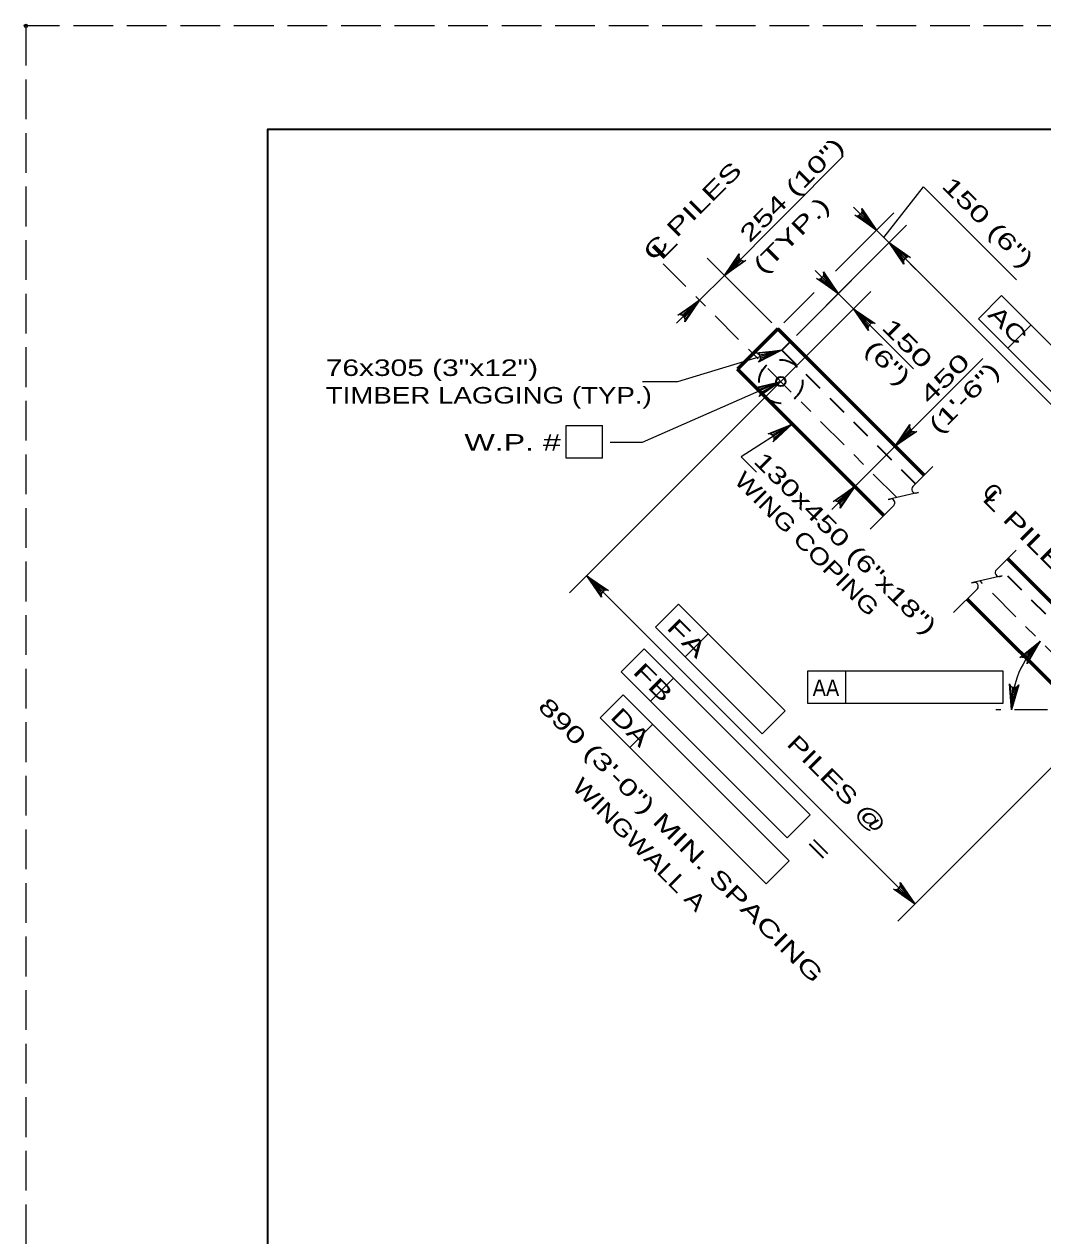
# Model space of a CAD drawing. Extents: x -6.4 to 73.1, y -66 to 0.
# Drawn here: x -0.01 to 7.37, y -8.76 to 0.01 of the extents above; entities that cross this region are included whole.
import ezdxf
from ezdxf.enums import TextEntityAlignment as Align

# ---------------------------------------------------------------- set-up
doc = ezdxf.new("R2010")
doc.units = 0
doc.header["$LTSCALE"] = 0.048
doc.header["$PDMODE"] = 32
doc.header["$PDSIZE"] = 0.024
for name, pattern in [('DOT_DASHED', [7.7, 5, -1.2, 0.3, -1.2]), ('LONG_DASHED', [7.5, 6, -1.5]), ('MEDIUM_DASHED', [4.5, 3, -1.5])]:
    doc.linetypes.add(name, pattern=pattern)
for name, color, linetype, lineweight in [('1', 7, 'Continuous', 13), ('2', 7, 'Continuous', 53), ('4', 7, 'Continuous', 25), ('5', 7, 'Continuous', 25), ('52', 7, 'Continuous', 25), ('63', 7, 'LONG_DASHED', 13)]:
    doc.layers.add(name, color=color, linetype=linetype, lineweight=lineweight)
doc.layers.add('62', color=7, linetype='Continuous')

msp = doc.modelspace()

# ---------------------------------------------------------------- hatches: boundary and pattern name
at = {"layer": '5'}
for points in [[(6.095, -1.38175), (6.06717, -1.40958), (6.16458, -1.47917)], [(6.3525, -1.63925), (6.32467, -1.66708), (6.25508, -1.56958)], [(5.13125, -1.70942), (5.15908, -1.73725), (5.06158, -1.80683)], [(5.81733, -1.84033), (5.7895, -1.86817), (5.88692, -1.93775)], [(4.784, -2.05658), (4.81183, -2.0845), (4.88142, -1.987)], [(6.09567, -2.11875), (6.06783, -2.14658), (5.99825, -2.04917)], [(5.47708, -2.34758), (5.36125, -2.37267), (5.367, -2.39142)], [(6.36883, -2.947), (6.39667, -2.97483), (6.29925, -3.04442)], [(5.9095, -3.40633), (5.93733, -3.43417), (6.00692, -3.33675)], [(4.16267, -4.05175), (4.13483, -4.07958), (4.06525, -3.98217)], [(6.37308, -6.26217), (6.34525, -6.29), (6.44267, -6.35958)]]:
    msp.add_hatch(color=256, dxfattribs=at).paths.add_polyline_path(points)

# ---------------------------------------------------------------- linework, layer by layer
at = {"layer": '1', "lineweight": 35}
msp.add_lwpolyline([(1.75, -21.25), (33.25, -21.25), (33.25, -0.75), (1.75, -0.75)], close=True, dxfattribs=at)
at = {"layer": '2'}
for p, q in [((5.44925, -2.1945), (5.15692, -2.48675)), ((6.50908, -3.25433), (5.44925, -2.1945)), ((6.21683, -3.54667), (5.15692, -2.48675)), ((7.91342, -4.65867), (7.1135, -3.85875)), ((7.74217, -5.072), (6.82125, -4.15108))]:
    msp.add_line(p, q, dxfattribs=at)
at = {"layer": '4', "linetype": 'MEDIUM_DASHED', "lineweight": 35}
for p, q in [((5.53975, -2.28492), (5.47708, -2.34758)), ((6.4465, -3.317), (5.47708, -2.34758)), ((8.08025, -4.95067), (7.05092, -3.92142))]:
    msp.add_line(p, q, dxfattribs=at)
msp.add_circle((5.4709, -2.5765), 0.15748, dxfattribs=at)
at = {"layer": '5'}
for p, q in [((5.06167, -1.80692), (5.9235, -0.94475)), ((6.1645, -1.47917), (5.99758, -1.31208)), ((5.86608, -1.77758), (6.28983, -1.35383)), ((5.58325, -2.24142), (6.38033, -1.44433)), ((6.37342, -1.68792), (6.16458, -1.47917)), ((8.62875, -3.94333), (6.25508, -1.56967)), ((5.40575, -2.151), (4.93633, -1.68158)), ((6.36642, -1.681), (6.44992, -1.7645)), ((4.88142, -1.987), (5.06158, -1.80683)), ((5.58325, -2.24142), (6.01217, -1.8125)), ((5.88692, -1.93775), (5.71992, -1.77075)), ((6.1235, -1.92383), (3.94, -4.10742)), ((4.88142, -1.987), (4.71442, -2.15408)), ((5.49275, -2.151), (5.71308, -1.93067)), ((5.88692, -1.93775), (5.99825, -2.04917)), ((7.06925, -1.95375), (6.90225, -2.12083)), ((7.06925, -1.95375), (8.27192, -3.15642)), ((5.99825, -2.04917), (6.43317, -2.48408)), ((6.90225, -2.12083), (8.10483, -3.32342)), ((7.28308, -2.16767), (7.11608, -2.33467)), ((6.29925, -3.04442), (6.93475, -2.40883)), ((3.91458, -3.12983), (3.91458, -2.89358)), ((3.91458, -2.89358), (4.17825, -2.89358)), ((4.17825, -3.12983), (4.17825, -2.89358)), ((6.00692, -3.33675), (6.29925, -3.04442)), ((6.28167, -3.02683), (6.4245, -3.16967)), ((4.17825, -3.12983), (3.91458, -3.12983)), ((6.57142, -3.192), (6.428, -3.3355)), ((5.98933, -3.31917), (6.13217, -3.462)), ((6.00692, -3.33675), (5.83992, -3.50375)), ((6.29058, -3.47283), (6.11783, -3.64567)), ((7.17617, -3.79608), (7.03275, -3.9395)), ((6.44267, -6.35958), (4.06525, -3.98217)), ((6.89542, -4.07683), (6.72258, -4.24967)), ((4.72975, -4.18875), (4.56275, -4.35575)), ((4.72975, -4.18875), (5.50158, -4.96058)), ((4.56275, -4.35575), (5.33458, -5.12758)), ((4.94358, -4.40258), (4.77658, -4.56958)), ((4.48025, -4.51117), (4.31325, -4.67825)), ((4.48025, -4.51117), (5.68292, -5.71383)), ((4.31325, -4.67825), (5.51583, -5.88083)), ((4.69408, -4.72508), (4.52708, -4.89208)), ((5.66692, -4.67183), (7.07892, -4.67183)), ((5.66692, -4.90808), (5.66692, -4.67183)), ((5.94067, -4.90808), (5.94067, -4.67183)), ((7.07892, -4.67183), (7.07892, -4.90808)), ((4.32917, -4.84467), (4.16217, -5.01167)), ((4.32917, -4.84467), (5.53183, -6.04733)), ((7.07892, -4.90808), (5.66692, -4.90808)), ((5.50158, -4.96058), (5.33458, -5.12758)), ((4.16217, -5.01167), (5.36483, -6.21433)), ((4.54308, -5.0585), (4.376, -5.22558)), ((7.43417, -5.36808), (6.31742, -6.48483)), ((5.68292, -5.71383), (5.51583, -5.88083)), ((5.53183, -6.04733), (5.36483, -6.21433))]:
    msp.add_line(p, q, dxfattribs=at)
at = {"layer": '5', "linetype": 'DOT_DASHED'}
for p, q in [((6.31042, -3.416), (4.61825, -1.72383)), ((7.93725, -5.04283), (6.91458, -4.02017)), ((18.74433, -4.95392), (7.02825, -4.95392))]:
    msp.add_line(p, q, dxfattribs=at)
at = {"layer": '5'}
for points in [[(6.21825, -1.53275), (6.5055, -1.16533), (7.17875, -1.83842)], [(6.1645, -1.47917), (6.008, -1.372), (6.02525, -1.37508), (6.03933, -1.3715), (6.04967, -1.36417), (6.057, -1.35383), (6.06058, -1.33975), (6.0575, -1.32258), (6.1645, -1.47917), (6.06058, -1.33975), (6.057, -1.35383), (6.1645, -1.47917), (6.04967, -1.36417), (6.03933, -1.3715), (6.1645, -1.47917), (6.02525, -1.37508)], [(6.25508, -1.56967), (6.41158, -1.67675), (6.39442, -1.67367), (6.38033, -1.67725), (6.37, -1.68458), (6.36267, -1.69492), (6.35908, -1.709), (6.36217, -1.72617), (6.25508, -1.56967), (6.35908, -1.709), (6.36267, -1.69492), (6.25508, -1.56967), (6.37, -1.68458), (6.38033, -1.67725), (6.25508, -1.56967), (6.39442, -1.67367)], [(5.06167, -1.80692), (5.16875, -1.65033), (5.16558, -1.66758), (5.16925, -1.68167), (5.17658, -1.692), (5.18692, -1.69933), (5.201, -1.70292), (5.21817, -1.69975), (5.06167, -1.80692), (5.201, -1.70292), (5.18692, -1.69933), (5.06167, -1.80692), (5.17658, -1.692), (5.16925, -1.68167), (5.06167, -1.80692), (5.16558, -1.66758)], [(5.88692, -1.93775), (5.73042, -1.83067), (5.74758, -1.83375), (5.76167, -1.83017), (5.772, -1.82283), (5.77933, -1.8125), (5.78292, -1.79842), (5.77983, -1.78125), (5.88692, -1.93775), (5.78292, -1.79842), (5.77933, -1.8125), (5.88692, -1.93775), (5.772, -1.82283), (5.76167, -1.83017), (5.88692, -1.93775), (5.74758, -1.83375)], [(4.88142, -1.987), (4.77433, -2.14358), (4.7775, -2.12633), (4.77383, -2.11225), (4.7665, -2.10192), (4.75617, -2.09458), (4.74208, -2.091), (4.72492, -2.09417), (4.88142, -1.987), (4.74208, -2.091), (4.75617, -2.09458), (4.88142, -1.987), (4.7665, -2.10192), (4.77383, -2.11225), (4.88142, -1.987), (4.7775, -2.12633)], [(5.99825, -2.04917), (6.15475, -2.15625), (6.13758, -2.15317), (6.1235, -2.15675), (6.11317, -2.16408), (6.10583, -2.17442), (6.10225, -2.1885), (6.10533, -2.20567), (5.99825, -2.04917), (6.10225, -2.1885), (6.10583, -2.17442), (5.99825, -2.04917), (6.11317, -2.16408), (6.1235, -2.15675), (5.99825, -2.04917), (6.13758, -2.15317)], [(5.47708, -2.34758), (4.722, -2.57792), (4.4685, -2.57792)], [(5.47708, -2.34758), (5.309, -2.43542), (5.31983, -2.42167), (5.32325, -2.40758), (5.32167, -2.395), (5.31592, -2.38367), (5.30525, -2.37383), (5.28858, -2.36858), (5.47708, -2.34758), (5.30525, -2.37383), (5.31592, -2.38367), (5.47708, -2.34758), (5.32167, -2.395), (5.32325, -2.40758), (5.47708, -2.34758), (5.31983, -2.42167)], [(5.47092, -2.5765), (4.46608, -3.01808), (4.23392, -3.01808)], [(5.55375, -2.88358), (5.18383, -3.12133), (5.29492, -3.23225)], [(6.29925, -3.04442), (6.40633, -2.88792), (6.40325, -2.90508), (6.40683, -2.91917), (6.41417, -2.9295), (6.4245, -2.93683), (6.43858, -2.94042), (6.45575, -2.93733), (6.29925, -3.04442), (6.43858, -2.94042), (6.4245, -2.93683), (6.29925, -3.04442), (6.41417, -2.9295), (6.40683, -2.91917), (6.29925, -3.04442), (6.40325, -2.90508)], [(6.00692, -3.33675), (5.89983, -3.49325), (5.90292, -3.47608), (5.89933, -3.462), (5.892, -3.45167), (5.88167, -3.44433), (5.86758, -3.44075), (5.85042, -3.44383), (6.00692, -3.33675), (5.86758, -3.44075), (5.88167, -3.44433), (6.00692, -3.33675), (5.892, -3.45167), (5.89933, -3.462), (6.00692, -3.33675), (5.90292, -3.47608)], [(6.45542, -3.383), (6.46917, -3.37975), (6.24758, -3.43033), (6.26242, -3.427)], [(4.06525, -3.98217), (4.22175, -4.08925), (4.20458, -4.08617), (4.1905, -4.08975), (4.18017, -4.09708), (4.17283, -4.10742), (4.16925, -4.1215), (4.17233, -4.13867), (4.06525, -3.98217), (4.16925, -4.1215), (4.17283, -4.10742), (4.06525, -3.98217), (4.18017, -4.09708), (4.1905, -4.08975), (4.06525, -3.98217), (4.20458, -4.08617)], [(7.06017, -3.98708), (7.07392, -3.98383), (6.85233, -4.03442), (6.86717, -4.031)], [(7.35033, -4.45592), (7.25675, -4.62092), (7.2585, -4.6035), (7.25367, -4.58983), (7.2455, -4.58008), (7.23458, -4.57367), (7.22025, -4.57125), (7.20333, -4.57583), (7.35033, -4.45592), (7.22025, -4.57125), (7.23458, -4.57367), (7.35033, -4.45592), (7.2455, -4.58008), (7.25367, -4.58983), (7.35033, -4.45592), (7.2585, -4.6035)], [(7.14258, -4.95417), (7.12675, -4.76517), (7.13525, -4.7805), (7.14692, -4.78908), (7.15908, -4.79258), (7.17175, -4.79167), (7.18492, -4.78558), (7.19625, -4.77233), (7.14258, -4.95417), (7.18492, -4.78558), (7.17175, -4.79167), (7.14258, -4.95417), (7.15908, -4.79258), (7.14692, -4.78908), (7.14258, -4.95417), (7.13525, -4.7805)], [(6.44267, -6.35958), (6.28617, -6.2525), (6.30333, -6.25558), (6.31742, -6.252), (6.32775, -6.24467), (6.33508, -6.23433), (6.33867, -6.22025), (6.33558, -6.20308), (6.44267, -6.35958), (6.33867, -6.22025), (6.33508, -6.23433), (6.44267, -6.35958), (6.32775, -6.24467), (6.31742, -6.252), (6.44267, -6.35958), (6.30333, -6.25558)]]:
    msp.add_lwpolyline(points, dxfattribs=at)
for points in [[(6.095, -1.38175), (6.06717, -1.40958), (6.16458, -1.47917)], [(6.3525, -1.63925), (6.32467, -1.66708), (6.25508, -1.56958)], [(5.13125, -1.70942), (5.15908, -1.73725), (5.06158, -1.80683)], [(5.81733, -1.84033), (5.7895, -1.86817), (5.88692, -1.93775)], [(4.784, -2.05658), (4.81183, -2.0845), (4.88142, -1.987)], [(6.09567, -2.11875), (6.06783, -2.14658), (5.99825, -2.04917)], [(5.47708, -2.34758), (5.36125, -2.37267), (5.367, -2.39142)], [(6.36883, -2.947), (6.39667, -2.97483), (6.29925, -3.04442)], [(5.9095, -3.40633), (5.93733, -3.43417), (6.00692, -3.33675)], [(4.16267, -4.05175), (4.13483, -4.07958), (4.06525, -3.98217)], [(6.37308, -6.26217), (6.34525, -6.29), (6.44267, -6.35958)]]:
    msp.add_lwpolyline(points, close=True, dxfattribs=at)
at = {"layer": '5', "lineweight": 35}
msp.add_circle((5.4709, -2.5765), 0.03402, dxfattribs=at)
at = {"layer": '5'}
for centre, radius, start, end in [((6.44807, -3.35556), 0.02841, 135, 285), ((6.26876, -3.45468), 0.02841, 320.32859, 102.86724), ((7.05285, -3.95961), 0.02841, 135, 285), ((6.87353, -4.05873), 0.02841, 320.32859, 102.86724), ((7.84317, -4.95393), 0.70061, 134.70069, 179.99908)]:
    msp.add_arc(centre, radius, start, end, dxfattribs=at)
at = {"layer": '52'}
for points in [[(5.47092, -2.5765), (5.31433, -2.6835), (5.3235, -2.66858), (5.32525, -2.65417), (5.32217, -2.64192), (5.31517, -2.63133), (5.30333, -2.62283), (5.28617, -2.6195), (5.47092, -2.5765), (5.30333, -2.62283), (5.31517, -2.63133), (5.47092, -2.5765), (5.32217, -2.64192), (5.32525, -2.65417), (5.47092, -2.5765), (5.3235, -2.66858)], [(5.55375, -2.88358), (5.41583, -3.01375), (5.4225, -2.99767), (5.422, -2.98308), (5.41708, -2.97142), (5.4085, -2.96208), (5.3955, -2.95558), (5.378, -2.955), (5.55375, -2.88358), (5.3955, -2.95558), (5.4085, -2.96208), (5.55375, -2.88358), (5.41708, -2.97142), (5.422, -2.98308), (5.55375, -2.88358), (5.4225, -2.99767)]]:
    msp.add_lwpolyline(points, dxfattribs=at)
at = {"layer": '62'}
msp.add_point((0, 0), dxfattribs=at)
at = {"layer": '63'}
msp.add_lwpolyline([(0, -22), (34, -22), (34, 0), (0, 0)], close=True, dxfattribs=at)

# ---------------------------------------------------------------- texts
at = {"layer": '5'}
for s, rotation, width, p in [('254 (10")', 45, 1.5, (5.59224, -1.22909)), ('(TYP.)', 45, 1.5, (5.58853, -1.55838)), ('L', 45, 2.1, (4.66707, -1.64259)), ('AC', 314.938, 1.4, (7.07313, -2.20954)), ('150', 315, 1.6, (6.34499, -2.34191)), ('(6")', 315, 1.5, (6.20366, -2.48341)), ('450', 45, 1.6, (6.69941, -2.59476)), ('(1\'-6")', 45, 1.5, (6.84082, -2.73618)), ('FA', 314.938, 1.55, (4.74779, -4.4767)), ('FB', 314.938, 1.55, (4.50363, -4.79679)), ('890 (3\'-0") MIN. SPACING', 315, 1.5, (4.70449, -5.94016)), ('DA', 314.938, 1.4, (4.33888, -5.12162)), ('PILES @', 314.938, 1.4, (5.83372, -5.53541)), ('WINGWALL A', 315, 1.25, (4.40274, -5.97166)), ('=', 314.938, 1.85, (5.70361, -6.00091))]:
    msp.add_text(s, height=0.12, rotation=rotation, dxfattribs=dict(at, width=width)).set_placement(p, align=Align.CENTER)
for s, rotation, width, p in [('C PILES', 45, 1.5, (4.54517, -1.7095)), ('150 (6")', 315, 1.5, (6.63025, -1.16592)), ('130x450 (6"x18")', 315, 1.45, (5.26642, -3.15933)), ('WING COPING', 315, 1.25, (5.125, -3.30075)), ('L PILES', 315, 1.55, (6.92367, -3.43292))]:
    msp.add_text(s, height=0.12, rotation=rotation, dxfattribs=dict(at, width=width)).set_placement(p)
for s, width, p in [('76x305 (3"x12")', 1.35, (2.17308, -2.53558)), ('TIMBER LAGGING (TYP.)', 1.25, (2.17308, -2.73558))]:
    msp.add_text(s, height=0.12, dxfattribs=dict(at, width=width)).set_placement(p)
for s, width, p in [('W.P. # ', 1.45, (3.55963, -3.07675)), ('AA', 0.9, (5.79767, -4.854))]:
    msp.add_text(s, height=0.12, dxfattribs=dict(at, width=width)).set_placement(p, align=Align.CENTER)
msp.add_text('C', height=0.12, rotation=315, dxfattribs=at).set_placement((6.92333, -3.3825))

doc.saveas('drawing.dxf')
